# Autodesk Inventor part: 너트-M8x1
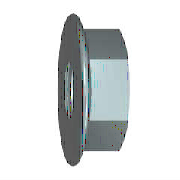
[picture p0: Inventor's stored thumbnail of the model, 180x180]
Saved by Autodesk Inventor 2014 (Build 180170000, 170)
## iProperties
Created: 2015-12
Part Number: 너트-M8x1
Material: 강철, 탄소
Description: 플랜지붙이 6각 너트 - 일반 스레드
Document SubType Name: Modeling
Standard: ISO 4161
Designer: mdu
Standard Revision: 2판 1999-03-15
Standards Organization: ISO
Language: ko-KR
Size Designation: M8
Categories: <MemberInstance><Categories><Category DisplayName="조임쇠" InternalName="e4da775c-781d-43d5-af7c-5136215cf5a6" Mnemonic="FSTN"><Category DisplayName="너트" InternalN
Density: 7.87 g/cm^3
Appearance: 노란색
Mass: 8.79821 g
Surface Area: 8.90186 cm^2
Volume: 1.11794 cm^3
Author: mdu
IsCustomPart: 1
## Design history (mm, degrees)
sketch "스케치1"
  geometry: L1 (-1.844, 0)-(9.641, 0) reference; L2 (3.107, 6.5)-(2.288, 8.257); L3 (3.107, 6.5)-(8, 6.5); L4 (8, 6.5)-(8, 0); L5 (3.107, 6.5)-(3.107, 0); L6 (0, -1.835)-(0, 11.01) reference; A1 r 1.2 centre (1.2, 7.75) between (2.288, 8.257) and (0, 7.75); 1 further point
  constraints: 8 end point, 3 point on line, 2 perpendicular, 2 point on circle, 2 tangent, 1 centre point, 1 parallel
  dimensions: "d2" = 13 diameter of L3 L1 (= SW); "d4" = 17.9 dimension on A1 L1 (= LADI); "d5" = 1.2 radius of A1 (= PHH); "d15" = 8 distance between parallel lines of L4 L6 (= KOH); "d16" = 25 deg angle of L6 L2 (= KEWI)
revolve "링" sketch "스케치1" stored, may be unused: angle "d8" = 90 deg
sketch "스케치2"
  geometry: L1 (-6.5, -3.753)-(-6.5, 3.753); L2 (-6.5, 3.753)-(0, 7.506); L3 (0, 7.506)-(6.5, 3.753); L4 (6.5, 3.753)-(6.5, -3.753); L5 (6.5, -3.753)-(0, -7.506); L6 (0, -7.506)-(-6.5, -3.753); C1 r 4.9 at (0, 0); C2 r 7.75 at (0, 0) reference; 1 further point
  constraints: 12 end point, 1 centre point, 1 coincident, 1 vertical, 11 other
  dimensions: "d6" = 15.01111 distance of L5.end L2.end (= 1.1547 x SW)
extrude "본체" join sketch "스케치2" distance "d7" = 8 (= KOH); taper "d9" = 0 deg
sketch "스케치3"
  geometry: L1 (2.638, 7.506)-(8, 7.506) reference; L2 (8, 3.753)-(8, 7.506) reference; L3 (0, -7.75)-(0, 7.75) reference; L4 (-1.6, 0)-(9.6, 0) reference; L5 (7.419, 7.506)-(8, 6.5)
  constraints: 2 end point, 2 point on line
  dimensions: "d10" = 30 deg angle of L2 L5 (= ANG1); "d11" = 13 diameter of L5.end L4 (= SW0)
revolve "모따기1" sketch "스케치3" stored, may be unused: angle "d24" = 90 deg
sketch "스케치4"
  geometry: C1 r 7.75 at (0, 0) reference; 1 further point
  constraints: 1 coincident
hole "스레드" sketch "스케치4" at (0, 0) diameter "d25" = 6.647; stored, may be unused: countersink angle "d29" = 82 deg, drill point angle "d31" = 118 deg; dims "d26" = 6, "d27" = 4, "d28" = 2, "d30" = 8
workaxis "Work Axis1"
workplane "Work Plane1"
body "Solid1"
chamfer "모따기2" distance "d12" = 0.67658 (= -0.5 x GD1 + 0.5 x NND); stored, may be unused: angle "d13" = 30 deg, second distance "d46" = 0.67658 (= -0.5 x GD1 + 0.5 x NND)
chamfer "모따기3" distance "d51" = 0.67658 (= -0.5 x GD1 + 0.5 x NND); stored, may be unused: second distance "d52" = 2, angle "d53" = 45 deg
other parameters: "ANG1" = 30 deg [user parameter; used in 1 equation term], "KEWI" = 25 deg [user parameter; used in 1 equation term], "NND" = 8 [user parameter; used in 4 equation terms], "LADI" = 17.9 [user parameter; used in 2 equation terms], "SW" = 13 [user parameter; used in 3 equation terms], "PHH" = 1.2 [user parameter; used in 3 equation terms], "KOH" = 8 (= NND) [user parameter; used in 2 equation terms], "SW0" = 13 [user parameter; used in 1 equation term], "GD1" = 6.64684 (computed from THREADDIA, PTC, TOA) [user parameter; used in 3 equation terms], "d1" = 17.9 (= LADI), "d3" = 1.2 (= PHH), "d45" = 0, "d47" = 0, "d49" = 0, "d54" = 0, "GUL" = 0.67658 (= 0.541266 x PTC) [user parameter], "TPU" = 8 (computed from PTC) [user parameter], "RR" = 1.2 (= PHH) [user parameter], "THREADDIA" = 8 [user parameter; used in 1 equation term], "TOA" = 30 deg [user parameter; used in 1 equation term], "PTC" = 1.25 [user parameter; used in 4 equation terms], "GAL" = 0.67658 (= 0.541266 x PTC) [user parameter], "E0" = 15.015 (= 1.155 x SW) [user parameter]
